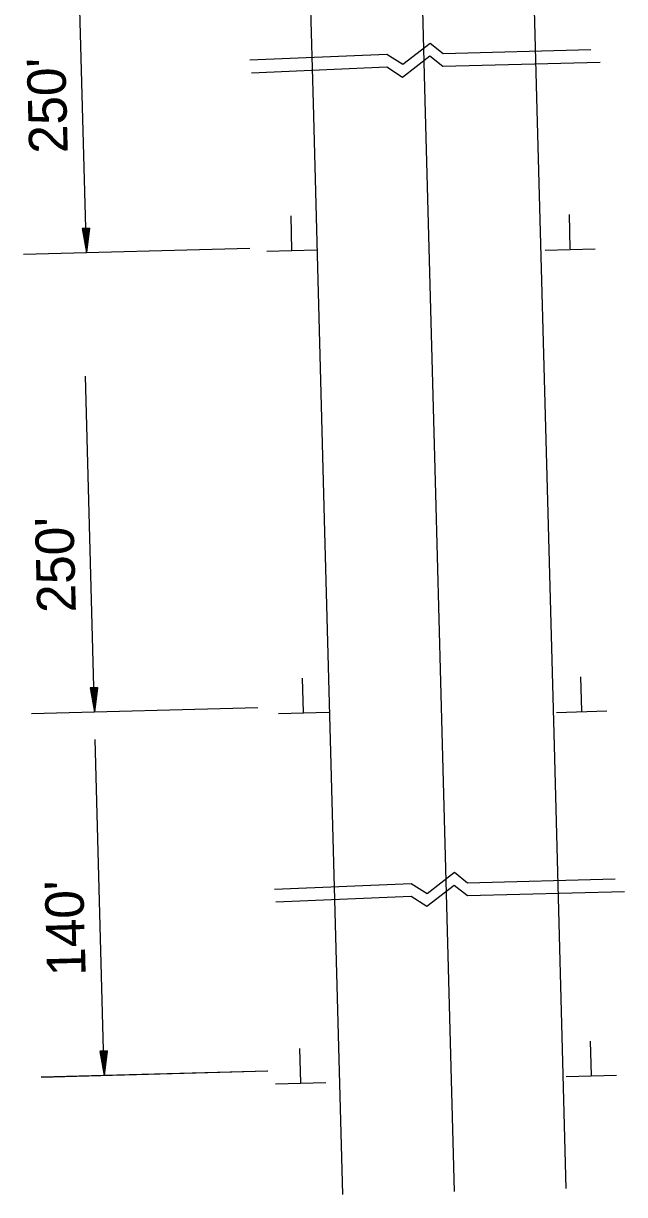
# Model space of a CAD drawing. Extents: x 1929624 to 1932607, y 596315 to 605533.
# Drawn here: x 1929789.6 to 1929885.3, y 598162.4 to 598348.6 of the extents above; entities that cross this region are included whole.
import ezdxf

# ---------------------------------------------------------------- set-up
doc = ezdxf.new("R2010")
doc.units = 0
doc.layers.add('Default', color=7, linetype='Continuous')

msp = doc.modelspace()

# ---------------------------------------------------------------- linework, layer by layer
at = {"layer": 'Default'}
for p, q in [((1929835.77, 598335.89), (1929833.87, 598406.48)), ((1929853.55, 598336.37), (1929851.66, 598406.95)), ((1929871.33, 598336.85), (1929869.44, 598407.43)), ((1929799.64, 598312.19), (1929798.2, 598365.57)), ((1929837.6, 598267.75), (1929835.77, 598335.89)), ((1929855.23, 598273.79), (1929853.55, 598336.37)), ((1929873.16, 598268.76), (1929871.33, 598336.85)), ((1929832.35, 598312.55), (1929832.2, 598318.02)), ((1929876.63, 598312.75), (1929876.48, 598318.21)), ((1929800.11, 598316.04), (1929798.96, 598316.01)), ((1929798.96, 598316.01), (1929799.64, 598312.19)), ((1929799.05, 598316.01), (1929799.62, 598312.83)), ((1929799.15, 598316.02), (1929799.6, 598313.49)), ((1929799.25, 598316.02), (1929799.58, 598314.13)), ((1929799.35, 598316.02), (1929799.57, 598314.78)), ((1929799.44, 598316.02), (1929799.55, 598315.42)), ((1929799.62, 598316.03), (1929799.55, 598315.42)), ((1929799.72, 598316.03), (1929799.57, 598314.78)), ((1929799.82, 598316.03), (1929799.58, 598314.13)), ((1929799.92, 598316.04), (1929799.6, 598313.49)), ((1929800.01, 598316.04), (1929799.62, 598312.83)), ((1929800.11, 598316.04), (1929799.64, 598312.19)), ((1929789.62, 598311.92), (1929825.64, 598312.89)), ((1929880.61, 598312.74), (1929872.61, 598312.53)), ((1929836.33, 598312.54), (1929828.33, 598312.33)), ((1929800.94, 598239.15), (1929799.5, 598292.54)), ((1929856.3, 598233.97), (1929855.23, 598273.79)), ((1929874.1, 598233.72), (1929873.16, 598268.76)), ((1929838.54, 598232.71), (1929837.6, 598267.75)), ((1929834.2, 598239.03), (1929834.05, 598244.49)), ((1929878.48, 598239.23), (1929878.33, 598244.69)), ((1929801.39, 598242.97), (1929800.24, 598242.94)), ((1929800.24, 598242.94), (1929800.92, 598239.11)), ((1929801.41, 598243), (1929800.26, 598242.97)), ((1929800.26, 598242.97), (1929800.94, 598239.15)), ((1929800.33, 598242.94), (1929800.9, 598239.76)), ((1929800.35, 598242.98), (1929800.92, 598239.79)), ((1929800.43, 598242.94), (1929800.88, 598240.42)), ((1929800.45, 598242.98), (1929800.9, 598240.45)), ((1929800.53, 598242.94), (1929800.86, 598241.05)), ((1929800.55, 598242.98), (1929800.88, 598241.09)), ((1929800.63, 598242.95), (1929800.85, 598241.7)), ((1929800.64, 598242.98), (1929800.87, 598241.74)), ((1929800.72, 598242.95), (1929800.83, 598242.34)), ((1929800.74, 598242.99), (1929800.85, 598242.38)), ((1929800.9, 598242.95), (1929800.83, 598242.34)), ((1929800.92, 598242.99), (1929800.85, 598242.38)), ((1929801, 598242.96), (1929800.85, 598241.7)), ((1929801.1, 598242.96), (1929800.86, 598241.05)), ((1929801.02, 598242.99), (1929800.87, 598241.74)), ((1929801.12, 598243), (1929800.88, 598241.09)), ((1929801.19, 598242.96), (1929800.88, 598240.42)), ((1929801.21, 598243), (1929800.9, 598240.45)), ((1929801.29, 598242.96), (1929800.9, 598239.76)), ((1929801.31, 598243), (1929800.92, 598239.79)), ((1929801.39, 598242.97), (1929800.92, 598239.11)), ((1929801.41, 598243), (1929800.94, 598239.15)), ((1929790.9, 598238.85), (1929826.92, 598239.81)), ((1929790.92, 598238.88), (1929826.94, 598239.85)), ((1929838.19, 598239.02), (1929830.18, 598238.8)), ((1929882.46, 598239.22), (1929874.46, 598239)), ((1929802.49, 598181.36), (1929801.05, 598234.75)), ((1929840.43, 598162.36), (1929838.54, 598232.71)), ((1929858.21, 598162.84), (1929856.3, 598233.97)), ((1929875.99, 598163.32), (1929874.1, 598233.72)), ((1929879.99, 598181.3), (1929879.84, 598186.76)), ((1929802.94, 598185.17), (1929801.79, 598185.14)), ((1929801.79, 598185.14), (1929802.47, 598181.32)), ((1929802.96, 598185.21), (1929801.81, 598185.18)), ((1929801.81, 598185.18), (1929802.49, 598181.36)), ((1929801.89, 598185.15), (1929802.45, 598181.96)), ((1929801.9, 598185.19), (1929802.47, 598182)), ((1929801.98, 598185.15), (1929802.43, 598182.62)), ((1929802, 598185.19), (1929802.45, 598182.66)), ((1929802.08, 598185.15), (1929802.42, 598183.26)), ((1929802.1, 598185.19), (1929802.43, 598183.3)), ((1929802.18, 598185.15), (1929802.4, 598183.91)), ((1929802.2, 598185.19), (1929802.42, 598183.95)), ((1929802.27, 598185.16), (1929802.38, 598184.55)), ((1929802.29, 598185.2), (1929802.4, 598184.59)), ((1929802.45, 598185.16), (1929802.38, 598184.55)), ((1929802.47, 598185.2), (1929802.4, 598184.59)), ((1929802.55, 598185.16), (1929802.4, 598183.91)), ((1929802.57, 598185.2), (1929802.42, 598183.95)), ((1929802.65, 598185.17), (1929802.42, 598183.26)), ((1929802.67, 598185.21), (1929802.43, 598183.3)), ((1929802.75, 598185.17), (1929802.43, 598182.62)), ((1929802.77, 598185.21), (1929802.45, 598182.66)), ((1929802.84, 598185.17), (1929802.45, 598181.96)), ((1929802.86, 598185.21), (1929802.47, 598182)), ((1929802.94, 598185.17), (1929802.47, 598181.32)), ((1929802.96, 598185.21), (1929802.49, 598181.36)), ((1929833.77, 598180.15), (1929833.62, 598185.62)), ((1929792.45, 598181.05), (1929828.47, 598182.02)), ((1929792.47, 598181.09), (1929828.49, 598182.06)), ((1929883.97, 598181.29), (1929875.97, 598181.07)), ((1929837.75, 598180.14), (1929829.75, 598179.93))]:
    msp.add_line(p, q, dxfattribs=at)
for points in [[(1929825.67, 598342.83), (1929847.45, 598343.74), (1929849.97, 598342.15), (1929854.31, 598345.51), (1929856.4, 598343.86), (1929879.89, 598344.48)], [(1929825.92, 598340.79), (1929847.42, 598341.7), (1929849.94, 598340.1), (1929854.28, 598343.46), (1929856.37, 598341.81), (1929881.39, 598342.48)], [(1929829.55, 598210.94), (1929851.33, 598211.86), (1929853.85, 598210.27), (1929858.19, 598213.62), (1929860.28, 598211.97), (1929883.77, 598212.6)], [(1929829.8, 598208.91), (1929851.3, 598209.81), (1929853.82, 598208.22), (1929858.16, 598211.58), (1929860.25, 598209.93), (1929885.27, 598210.59)]]:
    msp.add_lwpolyline(points, dxfattribs=at)

# ---------------------------------------------------------------- texts
for s, p in [("250'", (1929796.69, 598328.01)), ("250'", (1929797.98, 598254.97)), ("140'", (1929799.54, 598197.18))]:
    msp.add_text(s, height=6.14, rotation=91.5377, dxfattribs=at).set_placement(p)

doc.saveas('drawing.dxf')
